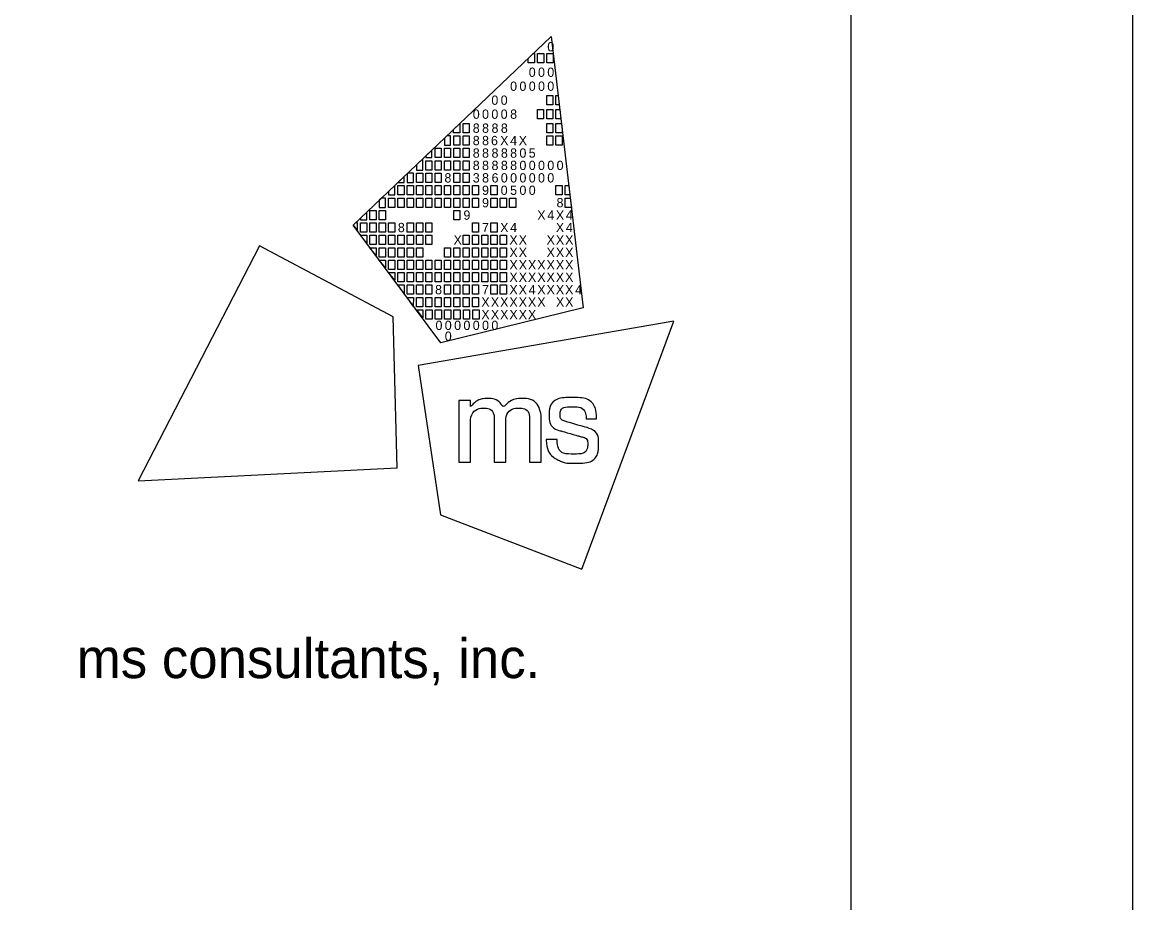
# Model space of a CAD drawing. Extents: x 0 to 69.3, y 0 to 22.
# Drawn here: x 32.03 to 34, y 2.551 to 4.111 of the extents above; entities that cross this region are included whole.
import ezdxf

# ---------------------------------------------------------------- set-up
doc = ezdxf.new("R2010")
doc.units = 0
for name, color, linetype in [('SH_Border', 7, 'Continuous'), ('SH_Cut_Line', 7, 'Continuous'), ('SH_Data', 7, 'Continuous')]:
    doc.layers.add(name, color=color, linetype=linetype)

msp = doc.modelspace()

# ---------------------------------------------------------------- linework, layer by layer
at = {"layer": 'SH_Border'}
for p, q in [((32.6175, 3.7519), (32.9688, 4.0861)), ((32.9688, 4.0861), (32.9688, 4.0861)), ((32.9688, 4.0861), (33.0253, 3.6052)), ((32.773, 3.543), (32.6175, 3.7519)), ((33.0253, 3.6052), (32.773, 3.543))]:
    msp.add_line(p, q, dxfattribs=at)
for points in [[(1.5, 21.5), (33.5, 21.5), (33.5, 0.5), (1.5, 0.5)], [(32.9279, 4.0472), (32.9369, 4.0558), (32.9389, 4.0558), (32.9389, 4.0393), (32.9279, 4.0393)], [(32.9444, 4.0558), (32.9554, 4.0558), (32.9554, 4.0393), (32.9444, 4.0393)], [(32.9609, 4.0558), (32.9719, 4.0558), (32.9719, 4.0393), (32.9609, 4.0393)], [(32.9606, 3.9815), (32.9716, 3.9815), (32.9716, 3.965), (32.9606, 3.965)], [(32.9771, 3.9815), (32.9811, 3.9815), (32.983, 3.965), (32.9771, 3.965)], [(32.9441, 3.9567), (32.9551, 3.9567), (32.9551, 3.9402), (32.9441, 3.9402)], [(32.9606, 3.9567), (32.9716, 3.9567), (32.9716, 3.9402), (32.9606, 3.9402)], [(32.9771, 3.9567), (32.984, 3.9567), (32.9859, 3.9402), (32.9771, 3.9402)], [(32.7953, 3.9211), (32.8064, 3.9316), (32.8064, 3.9154), (32.7953, 3.9154)], [(32.8123, 3.9319), (32.8233, 3.9319), (32.8233, 3.9154), (32.8123, 3.9154)], [(32.9606, 3.9319), (32.9716, 3.9319), (32.9716, 3.9154), (32.9606, 3.9154)], [(32.9771, 3.9319), (32.9869, 3.9319), (32.9881, 3.9218), (32.9881, 3.9154), (32.9771, 3.9154)], [(32.7958, 3.9099), (32.8068, 3.9099), (32.8068, 3.8934), (32.7958, 3.8934)], [(32.8123, 3.9099), (32.8233, 3.9099), (32.8233, 3.8934), (32.8123, 3.8934)], [(32.9606, 3.9099), (32.9716, 3.9099), (32.9716, 3.8934), (32.9606, 3.8934)], [(32.9771, 3.9099), (32.9881, 3.9099), (32.9881, 3.8934), (32.9771, 3.8934)], [(32.7627, 3.8879), (32.7737, 3.8879), (32.7737, 3.8714), (32.7627, 3.8714)], [(32.7793, 3.8879), (32.7903, 3.8879), (32.7903, 3.8714), (32.7793, 3.8714)], [(32.7958, 3.8879), (32.8068, 3.8879), (32.8068, 3.8714), (32.7958, 3.8714)], [(32.8123, 3.8879), (32.8233, 3.8879), (32.8233, 3.8714), (32.8123, 3.8714)], [(32.7462, 3.8659), (32.7572, 3.8659), (32.7572, 3.8494), (32.7462, 3.8494)], [(32.7627, 3.8659), (32.7737, 3.8659), (32.7737, 3.8494), (32.7627, 3.8494)], [(32.7793, 3.8659), (32.7903, 3.8659), (32.7903, 3.8494), (32.7793, 3.8494)], [(32.7958, 3.8659), (32.8068, 3.8659), (32.8068, 3.8494), (32.7958, 3.8494)], [(32.8123, 3.8659), (32.8233, 3.8659), (32.8233, 3.8494), (32.8123, 3.8494)], [(32.7297, 3.8439), (32.7407, 3.8439), (32.7407, 3.8273), (32.7297, 3.8273)], [(32.7462, 3.8439), (32.7572, 3.8439), (32.7572, 3.8273), (32.7462, 3.8273)], [(32.7627, 3.8439), (32.7737, 3.8439), (32.7737, 3.8273), (32.7627, 3.8273)], [(32.7958, 3.8439), (32.8068, 3.8439), (32.8068, 3.8273), (32.7958, 3.8273)], [(32.8123, 3.8439), (32.8233, 3.8439), (32.8233, 3.8273), (32.8123, 3.8273)], [(32.6967, 3.8218), (32.7077, 3.8218), (32.7077, 3.8053), (32.6967, 3.8053)], [(32.7132, 3.8218), (32.7242, 3.8218), (32.7242, 3.8053), (32.7132, 3.8053)], [(32.7297, 3.8218), (32.7407, 3.8218), (32.7407, 3.8053), (32.7297, 3.8053)], [(32.7462, 3.8218), (32.7572, 3.8218), (32.7572, 3.8053), (32.7462, 3.8053)], [(32.7627, 3.8218), (32.7737, 3.8218), (32.7737, 3.8053), (32.7627, 3.8053)], [(32.7793, 3.8218), (32.7903, 3.8218), (32.7903, 3.8053), (32.7793, 3.8053)], [(32.7958, 3.8218), (32.8068, 3.8218), (32.8068, 3.8053), (32.7958, 3.8053)], [(32.8123, 3.8218), (32.8233, 3.8218), (32.8233, 3.8053), (32.8123, 3.8053)], [(32.8288, 3.8218), (32.8398, 3.8218), (32.8398, 3.8053), (32.8288, 3.8053)], [(32.8618, 3.8218), (32.8728, 3.8218), (32.8728, 3.8053), (32.8618, 3.8053)], [(32.9771, 3.8218), (32.9881, 3.8218), (32.9881, 3.8053), (32.9771, 3.8053)], [(32.9935, 3.8218), (32.9998, 3.8218), (33.0018, 3.8053), (32.9935, 3.8053)], [(32.6802, 3.7998), (32.6912, 3.7998), (32.6912, 3.7833), (32.6802, 3.7833)], [(32.6967, 3.7998), (32.7077, 3.7998), (32.7077, 3.7833), (32.6967, 3.7833)], [(32.7132, 3.7998), (32.7242, 3.7998), (32.7242, 3.7833), (32.7132, 3.7833)], [(32.7297, 3.7998), (32.7407, 3.7998), (32.7407, 3.7833), (32.7297, 3.7833)], [(32.7462, 3.7998), (32.7572, 3.7998), (32.7572, 3.7833), (32.7462, 3.7833)], [(32.7627, 3.7998), (32.7737, 3.7998), (32.7737, 3.7833), (32.7627, 3.7833)], [(32.7793, 3.7998), (32.7903, 3.7998), (32.7903, 3.7833), (32.7793, 3.7833)], [(32.7958, 3.7998), (32.8068, 3.7998), (32.8068, 3.7833), (32.7958, 3.7833)], [(32.8123, 3.7998), (32.8233, 3.7998), (32.8233, 3.7833), (32.8123, 3.7833)], [(32.8288, 3.7998), (32.8398, 3.7998), (32.8398, 3.7833), (32.8288, 3.7833)], [(32.8618, 3.7998), (32.8728, 3.7998), (32.8728, 3.7833), (32.8618, 3.7833)], [(32.8783, 3.7998), (32.8893, 3.7998), (32.8893, 3.7833), (32.8783, 3.7833)], [(32.8947, 3.7998), (32.9057, 3.7998), (32.9057, 3.7833), (32.8947, 3.7833)], [(32.9935, 3.7998), (33.0024, 3.7998), (33.0044, 3.7833), (32.9935, 3.7833)], [(32.6471, 3.7778), (32.6581, 3.7778), (32.6581, 3.7613), (32.6471, 3.7613)], [(32.6637, 3.7778), (32.6747, 3.7778), (32.6747, 3.7613), (32.6637, 3.7613)], [(32.7958, 3.7778), (32.8068, 3.7778), (32.8068, 3.7613), (32.7958, 3.7613)], [(32.6306, 3.7558), (32.6416, 3.7558), (32.6416, 3.7393), (32.6306, 3.7393)], [(32.6471, 3.7558), (32.6581, 3.7558), (32.6581, 3.7393), (32.6471, 3.7393)], [(32.6637, 3.7558), (32.6747, 3.7558), (32.6747, 3.7393), (32.6637, 3.7393)], [(32.6802, 3.7558), (32.6912, 3.7558), (32.6912, 3.7393), (32.6802, 3.7393)], [(32.7132, 3.7558), (32.7242, 3.7558), (32.7242, 3.7393), (32.7132, 3.7393)], [(32.7297, 3.7558), (32.7407, 3.7558), (32.7407, 3.7393), (32.7297, 3.7393)], [(32.7462, 3.7558), (32.7572, 3.7558), (32.7572, 3.7393), (32.7462, 3.7393)], [(32.8288, 3.7558), (32.8398, 3.7558), (32.8398, 3.7393), (32.8288, 3.7393)], [(32.8618, 3.7558), (32.8728, 3.7558), (32.8728, 3.7393), (32.8618, 3.7393)], [(32.6306, 3.7338), (32.6416, 3.7338), (32.6416, 3.72)], [(32.6471, 3.7338), (32.6581, 3.7338), (32.6581, 3.7173), (32.6471, 3.7173)], [(32.6637, 3.7338), (32.6747, 3.7338), (32.6747, 3.7173), (32.6637, 3.7173)], [(32.6802, 3.7338), (32.6912, 3.7338), (32.6912, 3.7173), (32.6802, 3.7173)], [(32.6967, 3.7338), (32.7077, 3.7338), (32.7077, 3.7173), (32.6967, 3.7173)], [(32.7132, 3.7338), (32.7242, 3.7338), (32.7242, 3.7173), (32.7132, 3.7173)], [(32.7297, 3.7338), (32.7407, 3.7338), (32.7407, 3.7173), (32.7297, 3.7173)], [(32.7462, 3.7338), (32.7572, 3.7338), (32.7572, 3.7173), (32.7462, 3.7173)], [(32.8123, 3.7338), (32.8233, 3.7338), (32.8233, 3.7173), (32.8123, 3.7173)], [(32.8288, 3.7338), (32.8398, 3.7338), (32.8398, 3.7173), (32.8288, 3.7173)], [(32.8453, 3.7338), (32.8563, 3.7338), (32.8563, 3.7173), (32.8453, 3.7173)], [(32.8618, 3.7338), (32.8728, 3.7338), (32.8728, 3.7173), (32.8618, 3.7173)], [(32.8783, 3.7338), (32.8893, 3.7338), (32.8893, 3.7173), (32.8783, 3.7173)], [(32.6471, 3.7117), (32.6581, 3.7117), (32.6581, 3.698)], [(32.6637, 3.7117), (32.6747, 3.7117), (32.6747, 3.6952), (32.6637, 3.6952)], [(32.6802, 3.7117), (32.6912, 3.7117), (32.6912, 3.6952), (32.6802, 3.6952)], [(32.6967, 3.7117), (32.7077, 3.7117), (32.7077, 3.6952), (32.6967, 3.6952)], [(32.7132, 3.7117), (32.7242, 3.7117), (32.7242, 3.6952), (32.7132, 3.6952)], [(32.7297, 3.7117), (32.7407, 3.7117), (32.7407, 3.6952), (32.7297, 3.6952)], [(32.7793, 3.7117), (32.7903, 3.7117), (32.7903, 3.6952), (32.7793, 3.6952)], [(32.7958, 3.7117), (32.8068, 3.7117), (32.8068, 3.6952), (32.7958, 3.6952)], [(32.8123, 3.7117), (32.8233, 3.7117), (32.8233, 3.6952), (32.8123, 3.6952)], [(32.8288, 3.7117), (32.8398, 3.7117), (32.8398, 3.6952), (32.8288, 3.6952)], [(32.8453, 3.7117), (32.8563, 3.7117), (32.8563, 3.6952), (32.8453, 3.6952)], [(32.8618, 3.7117), (32.8728, 3.7117), (32.8728, 3.6952), (32.8618, 3.6952)], [(32.8783, 3.7117), (32.8893, 3.7117), (32.8893, 3.6952), (32.8783, 3.6952)], [(32.6637, 3.6897), (32.6747, 3.6897), (32.6747, 3.676)], [(32.6747, 3.6897), (32.6747, 3.6897), (32.6747, 3.6897)], [(32.6802, 3.6897), (32.6912, 3.6897), (32.6912, 3.6732), (32.6802, 3.6732)], [(32.6967, 3.6897), (32.7077, 3.6897), (32.7077, 3.6732), (32.6967, 3.6732)], [(32.7132, 3.6897), (32.7242, 3.6897), (32.7242, 3.6732), (32.7132, 3.6732)], [(32.7297, 3.6897), (32.7407, 3.6897), (32.7407, 3.6732), (32.7297, 3.6732)], [(32.7462, 3.6897), (32.7572, 3.6897), (32.7572, 3.6732), (32.7462, 3.6732)], [(32.7627, 3.6897), (32.7737, 3.6897), (32.7737, 3.6732), (32.7627, 3.6732)], [(32.7793, 3.6897), (32.7903, 3.6897), (32.7903, 3.6732), (32.7793, 3.6732)], [(32.7958, 3.6897), (32.8068, 3.6897), (32.8068, 3.6732), (32.7958, 3.6732)], [(32.8123, 3.6897), (32.8233, 3.6897), (32.8233, 3.6732), (32.8123, 3.6732)], [(32.8288, 3.6897), (32.8398, 3.6897), (32.8398, 3.6732), (32.8288, 3.6732)], [(32.8453, 3.6897), (32.8563, 3.6897), (32.8563, 3.6732), (32.8453, 3.6732)], [(32.8618, 3.6897), (32.8728, 3.6897), (32.8728, 3.6732), (32.8618, 3.6732)], [(32.8783, 3.6897), (32.8893, 3.6897), (32.8893, 3.6732), (32.8783, 3.6732)], [(32.6802, 3.6677), (32.6912, 3.6677), (32.6912, 3.654)], [(32.6967, 3.6677), (32.7077, 3.6677), (32.7077, 3.6512), (32.6967, 3.6512)], [(32.7132, 3.6677), (32.7242, 3.6677), (32.7242, 3.6512), (32.7132, 3.6512)], [(32.7297, 3.6677), (32.7407, 3.6677), (32.7407, 3.6512), (32.7297, 3.6512)], [(32.7462, 3.6677), (32.7572, 3.6677), (32.7572, 3.6512), (32.7462, 3.6512)], [(32.7627, 3.6677), (32.7737, 3.6677), (32.7737, 3.6512), (32.7627, 3.6512)], [(32.7793, 3.6677), (32.7903, 3.6677), (32.7903, 3.6512), (32.7793, 3.6512)], [(32.7958, 3.6677), (32.8068, 3.6677), (32.8068, 3.6512), (32.7958, 3.6512)], [(32.8123, 3.6677), (32.8233, 3.6677), (32.8233, 3.6512), (32.8123, 3.6512)], [(32.8288, 3.6677), (32.8398, 3.6677), (32.8398, 3.6512), (32.8288, 3.6512)], [(32.8453, 3.6677), (32.8563, 3.6677), (32.8563, 3.6512), (32.8453, 3.6512)], [(32.8618, 3.6677), (32.8728, 3.6677), (32.8728, 3.6512), (32.8618, 3.6512)], [(32.8783, 3.6677), (32.8893, 3.6677), (32.8893, 3.6512), (32.8783, 3.6512)], [(32.7077, 3.6305), (32.6965, 3.6457), (32.7077, 3.6457)], [(32.7132, 3.6457), (32.7242, 3.6457), (32.7242, 3.6292), (32.7132, 3.6292)], [(32.7297, 3.6457), (32.7407, 3.6457), (32.7407, 3.6292), (32.7297, 3.6292)], [(32.7462, 3.6457), (32.7572, 3.6457), (32.7572, 3.6292), (32.7462, 3.6292)], [(32.7793, 3.6457), (32.7903, 3.6457), (32.7903, 3.6292), (32.7793, 3.6292)], [(32.7958, 3.6457), (32.8068, 3.6457), (32.8068, 3.6292), (32.7958, 3.6292)], [(32.8123, 3.6457), (32.8233, 3.6457), (32.8233, 3.6292), (32.8123, 3.6292)], [(32.8288, 3.6457), (32.8398, 3.6457), (32.8398, 3.6292), (32.8288, 3.6292)], [(32.8618, 3.6457), (32.8728, 3.6457), (32.8728, 3.6292), (32.8618, 3.6292)], [(32.8783, 3.6457), (32.8893, 3.6457), (32.8893, 3.6292), (32.8783, 3.6292)], [(32.724, 3.6082), (32.7132, 3.6237), (32.7242, 3.6237)], [(32.7297, 3.6237), (32.7407, 3.6237), (32.7407, 3.6072), (32.7297, 3.6072)], [(32.7462, 3.6237), (32.7572, 3.6237), (32.7572, 3.6072), (32.7462, 3.6072)], [(32.7627, 3.6237), (32.7737, 3.6237), (32.7737, 3.6072), (32.7627, 3.6072)], [(32.7793, 3.6237), (32.7903, 3.6237), (32.7903, 3.6072), (32.7793, 3.6072)], [(32.7958, 3.6237), (32.8068, 3.6237), (32.8068, 3.6072), (32.7958, 3.6072)], [(32.8123, 3.6237), (32.8233, 3.6237), (32.8233, 3.6072), (32.8123, 3.6072)], [(32.8288, 3.6237), (32.8398, 3.6237), (32.8398, 3.6072), (32.8288, 3.6072)], [(32.7302, 3.6017), (32.7407, 3.6017), (32.7408, 3.5875)], [(32.7463, 3.6017), (32.7573, 3.6017), (32.7573, 3.5852), (32.7463, 3.5852)], [(32.763, 3.6017), (32.774, 3.6017), (32.774, 3.5852), (32.763, 3.5852)], [(32.7794, 3.6017), (32.7904, 3.6017), (32.7904, 3.5852), (32.7794, 3.5852)], [(32.796, 3.6017), (32.807, 3.6017), (32.807, 3.5852), (32.796, 3.5852)], [(32.8129, 3.6017), (32.8239, 3.6017), (32.8239, 3.5851), (32.8129, 3.5851)], [(32.8296, 3.6017), (32.8406, 3.6017), (32.8406, 3.5851), (32.8296, 3.5851)]]:
    msp.add_lwpolyline(points, close=True, dxfattribs=at)
for points in [[(32.7903, 3.9099), (32.7836, 3.9099), (32.7793, 3.9058), (32.7793, 3.8934), (32.7903, 3.8934), (32.7903, 3.9099)], [(32.7572, 3.8849), (32.7462, 3.8744), (32.7462, 3.8714), (32.7572, 3.8714), (32.7572, 3.8849)], [(32.7407, 3.8691), (32.7297, 3.8587), (32.7297, 3.8494), (32.7407, 3.8494), (32.7407, 3.8691)], [(32.7242, 3.8439), (32.7141, 3.8439), (32.7132, 3.843), (32.7132, 3.8273), (32.7242, 3.8273), (32.7242, 3.8439)], [(32.6912, 3.822), (32.6802, 3.8115), (32.6802, 3.8053), (32.6912, 3.8053), (32.6912, 3.822)], [(32.7077, 3.8377), (32.6968, 3.8273), (32.7077, 3.8273), (32.7077, 3.8377)], [(32.6747, 3.7998), (32.6679, 3.7998), (32.6637, 3.7958), (32.6637, 3.7833), (32.6747, 3.7833), (32.6747, 3.7998)], [(32.6416, 3.7749), (32.6306, 3.7644), (32.6306, 3.7613), (32.6416, 3.7613), (32.6416, 3.7749)], [(32.6251, 3.7558), (32.6216, 3.7558), (32.6175, 3.7519), (32.6251, 3.7417), (32.6251, 3.7558)], [(32.4512, 3.7149), (32.2359, 3.2988), (32.6956, 3.3215), (32.6884, 3.5892), (32.4512, 3.7149)], [(33.0229, 3.1422), (33.1859, 3.5814), (32.7324, 3.5029), (32.7722, 3.2381), (33.0229, 3.1422)]]:
    msp.add_lwpolyline(points, dxfattribs=at)
for points in [[(32.8048, 3.3315), (32.8048, 3.3315), (32.8048, 3.4409), (32.8048, 3.4409), (32.8048, 3.4409), (32.8255, 3.4409), (32.8255, 3.4409), (32.8255, 3.4409), (32.8255, 3.4297), (32.8255, 3.4297), (32.8346, 3.4399), (32.8457, 3.4445), (32.8555, 3.4445), (32.8688, 3.4445), (32.8791, 3.4372), (32.8837, 3.4266), (32.8915, 3.4381), (32.905, 3.4446), (32.9166, 3.4446), (32.9325, 3.4446), (32.9451, 3.435), (32.9494, 3.4213), (32.9494, 3.4212), (32.9494, 3.4212), (32.9494, 3.4212), (32.9501, 3.419), (32.9506, 3.4172), (32.9506, 3.4071), (32.9506, 3.4071), (32.9506, 3.3314), (32.9506, 3.3314), (32.9506, 3.3314), (32.9303, 3.3314), (32.9303, 3.3314), (32.9303, 3.3314), (32.9303, 3.4048), (32.9303, 3.4048), (32.9303, 3.4201), (32.9219, 3.4274), (32.911, 3.4274), (32.8995, 3.4274), (32.8879, 3.4171), (32.8879, 3.4001), (32.8879, 3.4001), (32.8879, 3.3315), (32.8879, 3.3315), (32.8879, 3.3315), (32.8674, 3.3315), (32.8674, 3.3315), (32.8674, 3.3315), (32.8674, 3.4059), (32.8674, 3.4059), (32.8674, 3.4203), (32.8588, 3.4274), (32.8496, 3.4274), (32.8384, 3.4274), (32.8254, 3.417), (32.8254, 3.3962), (32.8254, 3.3962), (32.8254, 3.3315), (32.8254, 3.3315), (32.8254, 3.3315), (32.8048, 3.3315), (32.8048, 3.3315)], [(32.9595, 3.3709), (32.9595, 3.3709), (32.9595, 3.3717), (32.9595, 3.3717), (32.9595, 3.3717), (32.9603, 3.3717), (32.9603, 3.3717), (32.9603, 3.3717), (32.9783, 3.3717), (32.9783, 3.3717), (32.9783, 3.3717), (32.9789, 3.3717), (32.9789, 3.3717), (32.9789, 3.3717), (32.979, 3.371), (32.979, 3.371), (32.9803, 3.3554), (32.9887, 3.346), (33.009, 3.346), (33.0273, 3.346), (33.0333, 3.3554), (33.0333, 3.3631), (33.0333, 3.3732), (33.0256, 3.3758), (33.0175, 3.378), (33.0175, 3.378), (32.987, 3.3867), (32.987, 3.3867), (32.972, 3.3909), (32.9648, 3.4019), (32.9648, 3.4142), (32.9648, 3.4303), (32.9768, 3.4462), (33.0052, 3.4462), (33.0348, 3.4462), (33.0489, 3.4285), (33.0489, 3.4095), (33.0489, 3.4095), (33.0489, 3.4087), (33.0489, 3.4087), (33.0489, 3.4087), (33.0482, 3.4087), (33.0482, 3.4087), (33.0482, 3.4087), (33.0312, 3.4087), (33.0312, 3.4087), (33.0312, 3.4087), (33.0305, 3.4087), (33.0305, 3.4087), (33.0305, 3.4087), (33.0305, 3.4094), (33.0305, 3.4094), (33.0301, 3.4208), (33.0226, 3.43), (33.0056, 3.43), (32.9891, 3.43), (32.9843, 3.4218), (32.9843, 3.4157), (32.9843, 3.4108), (32.9869, 3.4059), (32.9959, 3.4033), (32.9959, 3.4033), (33.0255, 3.3948), (33.0255, 3.3948), (33.0462, 3.3889), (33.0527, 3.3777), (33.0527, 3.3639), (33.0527, 3.3462), (33.041, 3.3298), (33.0087, 3.3298), (32.9952, 3.3298), (32.9877, 3.3321), (32.9823, 3.3348), (32.969, 3.3414), (32.9609, 3.3536), (32.9595, 3.3709)]]:
    msp.add_open_spline(points, degree=3, dxfattribs=at)
at = {"layer": 'SH_Cut_Line'}
msp.add_lwpolyline([(0, 0), (34, 0), (34, 22), (0, 22)], close=True, dxfattribs=at)
at = {"layer": 'SH_Data'}
msp.add_line((32.75, 3.5), (32.75, 3.5), dxfattribs=at)

# ---------------------------------------------------------------- texts
at = {"layer": 'SH_Border'}
for s, height, p in [('0', 0.0165, (32.9617, 4.0597)), ('0', 0.0165, (32.9288, 4.0145)), ('0', 0.0165, (32.9452, 4.0145)), ('0', 0.0165, (32.9617, 4.0145)), ('0', 0.0165, (32.8958, 3.9897)), ('0', 0.0165, (32.9123, 3.9897)), ('0', 0.0165, (32.9288, 3.9897)), ('0', 0.0165, (32.9452, 3.9897)), ('0', 0.0165, (32.9617, 3.9897)), ('0', 0.0165, (32.8625, 3.965)), ('0', 0.0165, (32.879, 3.965)), ('0', 0.0165, (32.8295, 3.9402)), ('0', 0.0165, (32.846, 3.9402)), ('0', 0.0165, (32.8625, 3.9402)), ('0', 0.0165, (32.879, 3.9402)), ('8', 0.0165, (32.8958, 3.9402)), ('8', 0.0165, (32.8295, 3.9154)), ('8', 0.0165, (32.846, 3.9154)), ('8', 0.0165, (32.8628, 3.9154)), ('8', 0.0165, (32.8793, 3.9154)), ('8', 0.0165, (32.8295, 3.8934)), ('8', 0.0165, (32.846, 3.8934)), ('6', 0.0165, (32.8618, 3.8934)), ('X', 0.0165, (32.8781, 3.8934)), ('4', 0.0165, (32.8958, 3.8934)), ('X', 0.0165, (32.911, 3.8934)), ('8', 0.0165, (32.8295, 3.8713)), ('8', 0.0165, (32.846, 3.8713)), ('8', 0.0165, (32.8628, 3.8713)), ('8', 0.0165, (32.8794, 3.8713)), ('8', 0.0165, (32.8958, 3.8713)), ('0', 0.0165, (32.9123, 3.8713)), ('5', 0.0165, (32.9287, 3.8713)), ('8', 0.0165, (32.8295, 3.8494)), ('8', 0.0165, (32.846, 3.8494)), ('8', 0.0165, (32.8628, 3.8494)), ('8', 0.0165, (32.8794, 3.8494)), ('8', 0.0165, (32.8958, 3.8494)), ('0', 0.0165, (32.9123, 3.8494)), ('0', 0.0165, (32.9288, 3.8494)), ('0', 0.0165, (32.9452, 3.8494)), ('0', 0.0165, (32.9617, 3.8494)), ('0', 0.0165, (32.9782, 3.8494)), ('8', 0.0165, (32.7793, 3.8273)), ('3', 0.0165, (32.8295, 3.8273)), ('8', 0.0165, (32.846, 3.8273)), ('6', 0.0165, (32.8629, 3.8273)), ('0', 0.0165, (32.8793, 3.8273)), ('0', 0.0165, (32.8958, 3.8273)), ('0', 0.0165, (32.9123, 3.8273)), ('0', 0.0165, (32.9288, 3.8273)), ('0', 0.0165, (32.9452, 3.8273)), ('0', 0.0165, (32.9617, 3.8273)), ('9', 0.0165, (32.846, 3.8053)), ('0', 0.0165, (32.879, 3.8053)), ('5', 0.0165, (32.8957, 3.8053)), ('0', 0.0165, (32.9123, 3.8053)), ('0', 0.0165, (32.9288, 3.8053)), ('9', 0.0165, (32.846, 3.7833)), ('8', 0.0165, (32.9781, 3.7833)), ('9', 0.0165, (32.813, 3.7613)), ('X', 0.0165, (32.9439, 3.7613)), ('4', 0.0165, (32.9617, 3.7613)), ('X', 0.0165, (32.9769, 3.7613)), ('4', 0.0165, (32.9946, 3.7613)), ('8', 0.0165, (32.6967, 3.7393)), ('7', 0.0165, (32.846, 3.7393)), ('X', 0.0165, (32.8781, 3.7393)), ('4', 0.0165, (32.8958, 3.7393)), ('X', 0.0165, (32.9769, 3.7393)), ('4', 0.0165, (32.9946, 3.7393)), ('X', 0.0165, (32.7955, 3.7173)), ('X', 0.0165, (32.8945, 3.7173)), ('X', 0.0165, (32.911, 3.7173)), ('X', 0.0165, (32.9604, 3.7173)), ('X', 0.0165, (32.9769, 3.7173)), ('X', 0.0165, (32.9933, 3.7173)), ('X', 0.0165, (32.8945, 3.6952)), ('X', 0.0165, (32.911, 3.6952)), ('X', 0.0165, (32.9604, 3.6952)), ('X', 0.0165, (32.9769, 3.6952)), ('X', 0.0165, (32.9933, 3.6952)), ('X', 0.0165, (32.8945, 3.6732)), ('X', 0.0165, (32.911, 3.6732)), ('X', 0.0165, (32.9274, 3.6732)), ('X', 0.0165, (32.9439, 3.6732)), ('X', 0.0165, (32.9604, 3.6732)), ('X', 0.0165, (32.9769, 3.6732)), ('X', 0.0165, (32.9933, 3.6732)), ('X', 0.0165, (32.8945, 3.6512)), ('X', 0.0165, (32.911, 3.6512)), ('X', 0.0165, (32.9274, 3.6512)), ('X', 0.0165, (32.9439, 3.6512)), ('X', 0.0165, (32.9604, 3.6512)), ('X', 0.0165, (32.9769, 3.6512)), ('X', 0.0165, (32.9933, 3.6512)), ('8', 0.0165, (32.7627, 3.6292)), ('7', 0.0165, (32.846, 3.6292)), ('X', 0.0165, (32.8945, 3.6292)), ('X', 0.0165, (32.911, 3.6292)), ('4', 0.0165, (32.9288, 3.6292)), ('X', 0.0165, (32.9439, 3.6292)), ('X', 0.0165, (32.9604, 3.6292)), ('X', 0.0165, (32.9769, 3.6292)), ('X', 0.0165, (32.9933, 3.6292)), ('4', 0.0165, (33.0111, 3.6292)), ('X', 0.0165, (32.8447, 3.6072)), ('X', 0.0165, (32.8616, 3.6072)), ('X', 0.0165, (32.878, 3.6072)), ('X', 0.0165, (32.8945, 3.6072)), ('X', 0.0165, (32.911, 3.6072)), ('X', 0.0165, (32.9274, 3.6072)), ('X', 0.0165, (32.9439, 3.6072)), ('X', 0.0165, (32.9771, 3.6072)), ('X', 0.0165, (32.9933, 3.6072)), ('X', 0.0165, (32.8447, 3.5851)), ('X', 0.0165, (32.8616, 3.5851)), ('X', 0.0165, (32.878, 3.5851)), ('X', 0.0165, (32.8945, 3.5851)), ('X', 0.0165, (32.911, 3.5851)), ('X', 0.0165, (32.9274, 3.5851)), ('0', 0.0165, (32.7634, 3.5659)), ('0', 0.0165, (32.7799, 3.5659)), ('0', 0.0165, (32.7965, 3.5659)), ('0', 0.0165, (32.813, 3.5659)), ('0', 0.0165, (32.8295, 3.5659)), ('0', 0.0165, (32.846, 3.5659)), ('0', 0.0165, (32.8625, 3.5659)), ('0', 0.0165, (32.7799, 3.5467)), ('ms consultants, inc.', 0.07, (32.1273, 2.9489))]:
    msp.add_text(s, height=height, rotation=360, dxfattribs=at).set_placement(p)

doc.saveas('drawing.dxf')
